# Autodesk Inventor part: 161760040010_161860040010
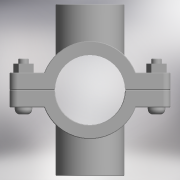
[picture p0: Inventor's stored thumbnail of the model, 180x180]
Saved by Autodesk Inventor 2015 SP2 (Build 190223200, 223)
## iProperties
Created: 2017-05
Part Number: 161760040010_161860040010
Material: Generic
Description: PLASSON DOUBLE SADDLE 40-1"
Document SubType Name: Modeling
Designer: KIM
Density: 1 g/cm^3
Appearance: Default
Author: KIM
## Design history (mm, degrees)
derived "16176.ipt"
feature "Solid1::16176.ipt"
feature "Solid2::16176.ipt"
tag "TaggingFeature1"
body "Solid1"
body "Solid2"
other parameters: "d0" = 56, "d1" = 92, "d5" = 0, "d6" = 4.6, "d7" = 92, "d8" = 0.1, "d10" = 0, "d11" = 0.4, "d20" = 0.4, "d23" = 0.4, "d37" = 8, "d38" = 28, "d39" = 0, "d40" = 3, "d41" = 5, "d42" = 0, "d43" = 6, "d44" = 3, "d45" = 0, "d46" = 0.4, "d52" = 30.291, "d53" = 21, "d54" = 0, "d55" = 25, "d57" = 0, "d58" = 43.2, "d60" = 0, "d66" = 0, "d67" = 98, "d68" = 39.3783, "d69" = 30.291, "d70" = 21, "d71" = 0, "d72" = 25, "d74" = 0, "d75" = 0.4, "B_" = 25, "G_" = 30.291, "A_" = 49, "L_" = 92, "l_2" = 21
